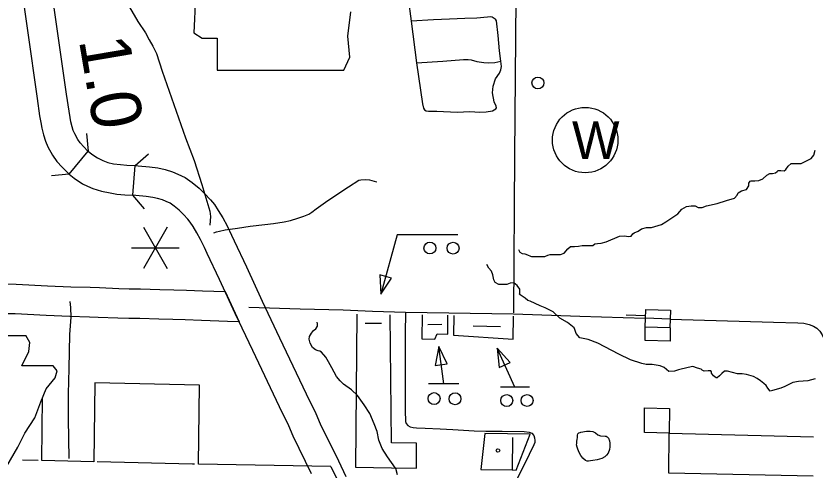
# Model space of a CAD drawing. Extents: x 1382482 to 1385815, y 1168351 to 1170484.
# Drawn here: x 1384529.1 to 1384797.7, y 1168845.5 to 1168998.2 of the extents above; entities that cross this region are included whole.
import ezdxf

# ---------------------------------------------------------------- set-up
doc = ezdxf.new("R2010")
doc.units = 0
for name, color, linetype in [('10', 7, 'Continuous'), ('15', 7, 'Continuous'), ('21', 7, 'Continuous'), ('35', 7, 'Continuous'), ('37', 7, 'Continuous'), ('48', 7, 'Continuous'), ('5', 7, 'Continuous'), ('57', 7, 'Continuous'), ('6', 7, 'Continuous'), ('Default', 7, 'Continuous')]:
    doc.layers.add(name, color=color, linetype=linetype)

msp = doc.modelspace()

# ---------------------------------------------------------------- linework, layer by layer
at = {"layer": '10'}
for points in [[(1384484.87, 1168906.51), (1384491.93, 1168906.82), (1384503.41, 1168907.42), (1384514, 1168907.87), (1384517.48, 1168907.94), (1384520.85, 1168908.05), (1384525.12, 1168908.05), (1384529.2, 1168908.01), (1384539.72, 1168907.46), (1384547.53, 1168907.11), (1384554.1, 1168906.93), (1384557.15, 1168906.82), (1384563.66, 1168906.54), (1384567.21, 1168906.44), (1384570.95, 1168906.4), (1384577.43, 1168906.23), (1384582.14, 1168906.12), (1384586.38, 1168905.98), (1384591.81, 1168905.76), (1384599.4, 1168905.49), (1384604.12, 1168895.31)], [(1384604.12, 1168895.31), (1384600.17, 1168895.45), (1384591.44, 1168895.77), (1384586.02, 1168895.98), (1384581.86, 1168896.12), (1384577.18, 1168896.23), (1384570.77, 1168896.4), (1384567.02, 1168896.44), (1384563.3, 1168896.55), (1384556.75, 1168896.83), (1384553.79, 1168896.94), (1384547.18, 1168897.11), (1384539.24, 1168897.47), (1384528.89, 1168898.01), (1384525.07, 1168898.05), (1384521.01, 1168898.05), (1384517.74, 1168897.94), (1384514.31, 1168897.87), (1384503.88, 1168897.43), (1384492.41, 1168896.83), (1384485.31, 1168896.52)]]:
    msp.add_lwpolyline(points, dxfattribs=at)
at = {"layer": '15'}
for points in [[(1384535.02, 1169049.94), (1384533.37, 1169049.02), (1384531.6, 1169048.43), (1384529.89, 1169048.1), (1384528.02, 1169048.07), (1384526.27, 1169048.27), (1384525.11, 1169048.58), (1384525.72, 1169044.13), (1384526.78, 1169036.05), (1384531.2, 1169005.95), (1384532.97, 1168993.24), (1384536.19, 1168970.39), (1384537.07, 1168964.62), (1384537.44, 1168962.3), (1384537.78, 1168960.47), (1384538.34, 1168958.17), (1384539.05, 1168956.06), (1384539.87, 1168954.17), (1384541.35, 1168951.36), (1384542.89, 1168949.25), (1384544.61, 1168947.32), (1384546.4, 1168945.48), (1384547.01, 1168944.97), (1384553.41, 1168952.66)], [(1384553.41, 1168952.66), (1384553.21, 1168952.83), (1384551.93, 1168954.14), (1384550.68, 1168955.54), (1384549.85, 1168956.67), (1384548.89, 1168958.5), (1384548.39, 1168959.64), (1384547.96, 1168960.94), (1384547.56, 1168962.59), (1384547.29, 1168964), (1384546.95, 1168966.15), (1384546.08, 1168971.84), (1384542.87, 1168994.63), (1384541.1, 1169007.37), (1384536.68, 1169037.42), (1384535.63, 1169045.46), (1384535.02, 1169049.94)], [(1384553.41, 1168952.66), (1384554.61, 1168951.66), (1384556.49, 1168950.44), (1384557.43, 1168949.97), (1384558.35, 1168949.57), (1384560.03, 1168948.89), (1384561.87, 1168948.5), (1384564.28, 1168948.18), (1384566.41, 1168948.02), (1384569.14, 1168947.83)], [(1384568.43, 1168937.86), (1384569.14, 1168947.83), (1384570.19, 1168947.76), (1384573.99, 1168947.4), (1384576.77, 1168947.05), (1384579.3, 1168946.52), (1384581.7, 1168945.73), (1384583.57, 1168945), (1384585.93, 1168943.88), (1384588.38, 1168942.21), (1384590.64, 1168940.31), (1384592.5, 1168938.5), (1384594.54, 1168936.35), (1384595.79, 1168934.72), (1384597.13, 1168932.73), (1384598.61, 1168930.25), (1384600.07, 1168927.56), (1384601.56, 1168924.49), (1384602.44, 1168922.51), (1384606.59, 1168913.8), (1384611.87, 1168902.32), (1384617.71, 1168889.98), (1384626.67, 1168871.09), (1384629.95, 1168864.5), (1384631.41, 1168861.06), (1384637.48, 1168848.56), (1384640.01, 1168843.27)], [(1384547.01, 1168944.97), (1384548.67, 1168943.59), (1384551.52, 1168941.74), (1384553.2, 1168940.9), (1384554.92, 1168940.16), (1384557.85, 1168939.29), (1384560.74, 1168938.66), (1384563.02, 1168938.24), (1384565.7, 1168938.05), (1384568.43, 1168937.86)], [(1384628.47, 1168844.22), (1384622.3, 1168856.93), (1384620.86, 1168860.32), (1384617.67, 1168866.72), (1384608.68, 1168885.7), (1384602.81, 1168898.09), (1384597.53, 1168909.56), (1384593.36, 1168918.33), (1384592.49, 1168920.28), (1384591.18, 1168922.99), (1384589.92, 1168925.3), (1384588.69, 1168927.37), (1384587.67, 1168928.88), (1384586.93, 1168929.85), (1384585.39, 1168931.46), (1384583.92, 1168932.89), (1384582.33, 1168934.23), (1384580.93, 1168935.19), (1384579.61, 1168935.82), (1384578.33, 1168936.31), (1384576.7, 1168936.84), (1384575.12, 1168937.18), (1384572.91, 1168937.45), (1384569.36, 1168937.79), (1384568.43, 1168937.86)]]:
    msp.add_lwpolyline(points, dxfattribs=at)
at = {"layer": '21'}
for p, q in [((1384590.29, 1169023.23), (1384588.94, 1168992.44)), ((1384640.71, 1168991.42), (1384641.72, 1168999.54)), ((1384588.94, 1168992.44), (1384591.65, 1168990.74)), ((1384591.65, 1168990.74), (1384596.72, 1168990.74)), ((1384596.72, 1168990.74), (1384596.72, 1168979.92)), ((1384641.38, 1168984.32), (1384640.71, 1168991.42)), ((1384639.35, 1168979.92), (1384641.38, 1168984.32)), ((1384596.72, 1168979.92), (1384639.35, 1168979.92)), ((1384533.8, 1168888.37), (1384532.39, 1168890.7)), ((1384533.46, 1168885.32), (1384533.8, 1168888.37)), ((1384531.09, 1168880.58), (1384533.46, 1168885.32)), ((1384541.58, 1168880.58), (1384531.09, 1168880.58)), ((1384542.93, 1168878.89), (1384541.58, 1168880.58)), ((1384542.25, 1168876.52), (1384542.93, 1168878.89)), ((1384539.21, 1168872.8), (1384542.25, 1168876.52)), ((1384537.52, 1168868.4), (1384539.21, 1168872.8)), ((1384535.49, 1168862.99), (1384537.52, 1168868.4)), ((1384532.1, 1168857.91), (1384535.49, 1168862.99)), ((1384529.74, 1168853.18), (1384532.1, 1168857.91)), ((1384526.01, 1168846.75), (1384529.74, 1168853.18))]:
    msp.add_line(p, q, dxfattribs=at)
msp.add_lwpolyline([(1384471.54, 1168890.73), (1384532.39, 1168890.7)], dxfattribs=at)
at = {"layer": '35'}
for points in [[(1384698.02, 1168919.63), (1384698.5, 1168918.76), (1384699.28, 1168918.29), (1384700.15, 1168918.21), (1384701.01, 1168917.9), (1384702.04, 1168917.42), (1384702.43, 1168917.34), (1384703.45, 1168917.34), (1384704.87, 1168917.27), (1384706.91, 1168917.34), (1384707.94, 1168917.74), (1384708.65, 1168917.97), (1384709.67, 1168917.97), (1384710.22, 1168917.97), (1384711.16, 1168917.97), (1384712.19, 1168917.97), (1384713.37, 1168918.45), (1384714.63, 1168919.86), (1384715.49, 1168920.65), (1384715.88, 1168920.65), (1384716.83, 1168920.65), (1384718.25, 1168920.73), (1384719.43, 1168921.04), (1384720.29, 1168921.04), (1384721.79, 1168921.04), (1384723.04, 1168921.04), (1384723.75, 1168921.52), (1384724.54, 1168921.67), (1384725.8, 1168921.75), (1384727.53, 1168922.22), (1384732.01, 1168924.11), (1384733.75, 1168924.27), (1384734.85, 1168924.04), (1384735.95, 1168924.11), (1384736.5, 1168924.9), (1384736.89, 1168925.29), (1384738.23, 1168925.77), (1384739.33, 1168926.55), (1384741.06, 1168927.03), (1384742.79, 1168927.03), (1384746.1, 1168928.05), (1384747.59, 1168928.91), (1384749.6, 1168930.33), (1384751.57, 1168931.67), (1384752.9, 1168933.17), (1384754.48, 1168934.11), (1384756.13, 1168934.35), (1384757.47, 1168934.35), (1384758.41, 1168933.8), (1384759.75, 1168933.8), (1384761.24, 1168934.27), (1384764.79, 1168935.13), (1384767.93, 1168936.08), (1384770.69, 1168936.94), (1384771.55, 1168937.89), (1384771.87, 1168938.75), (1384772.97, 1168939.38), (1384774.7, 1168939.78), (1384775.41, 1168941.04), (1384775.49, 1168941.98), (1384775.88, 1168942.61), (1384776.27, 1168942.77), (1384777.45, 1168942.77), (1384778.79, 1168942.85), (1384780.13, 1168943.4), (1384781.54, 1168944.66), (1384782.49, 1168945.21), (1384783.43, 1168945.21), (1384784.38, 1168945.37), (1384785.01, 1168945.84), (1384785.32, 1168946.15), (1384786.19, 1168946.15), (1384787.29, 1168946.07), (1384787.92, 1168946.55), (1384788.7, 1168947.65), (1384789.65, 1168948.51), (1384790.83, 1168948.59), (1384793.03, 1168948.51), (1384793.98, 1168948.99), (1384796.47, 1168950.22), (1384797.34, 1168951.4), (1384797.73, 1168953.05)], [(1384755.1, 1168879.93), (1384751.87, 1168879.23), (1384750.5, 1168878.71), (1384748.61, 1168878.65), (1384746.98, 1168880.02), (1384745.68, 1168880.54), (1384742.93, 1168880.93), (1384740.98, 1168880.93), (1384739.49, 1168881.29), (1384735.64, 1168882.53), (1384731.71, 1168884.45), (1384724.67, 1168888.11), (1384721.47, 1168889.35), (1384718.6, 1168889.93), (1384717.37, 1168891.44), (1384716.92, 1168892.74), (1384716.76, 1168893.29), (1384714.54, 1168895.12), (1384711.89, 1168896.52), (1384709.67, 1168898.68), (1384706.99, 1168900.05), (1384705.36, 1168900.7), (1384703.62, 1168901.48), (1384701.99, 1168902.26), (1384701.14, 1168902.53), (1384700.23, 1168903.24), (1384698.27, 1168904.61), (1384698.53, 1168904.81), (1384698.47, 1168906.31), (1384697.56, 1168907.55), (1384696.45, 1168908.4), (1384695.27, 1168908.33), (1384694.07, 1168907.91), (1384691.46, 1168907.88), (1384690.15, 1168908.53), (1384689.7, 1168909.41), (1384689.43, 1168911.11), (1384688.95, 1168912.31), (1384688.1, 1168913.36), (1384687.38, 1168914.6)], [(1384633.24, 1168883.46), (1384631.76, 1168885.14), (1384631.26, 1168885.41), (1384630.64, 1168885.56), (1384629.76, 1168885.87), (1384628.79, 1168886.64), (1384627.95, 1168888.14), (1384627.68, 1168889.45), (1384627.83, 1168890.41), (1384628.45, 1168891.53), (1384629.1, 1168892.38), (1384629.87, 1168892.99), (1384630.45, 1168893.88), (1384630.49, 1168894.61), (1384630.39, 1168895.26)], [(1384656.69, 1168846.16), (1384653.97, 1168849.95), (1384652.18, 1168852.73), (1384651.1, 1168855.58), (1384650.56, 1168858.43), (1384649.56, 1168861.05), (1384648.1, 1168864.52), (1384646.18, 1168867.37), (1384643.94, 1168870.6), (1384641.94, 1168872.45), (1384639.25, 1168874.37), (1384638.09, 1168875.45), (1384636.86, 1168876.99), (1384635.32, 1168879.84), (1384634.16, 1168881.92), (1384633.24, 1168883.46), (1384633.22, 1168883.52)], [(1384797.72, 1168876.14), (1384795.31, 1168875.43), (1384792.18, 1168875.3), (1384790.29, 1168874.91), (1384788.72, 1168874.19), (1384787.55, 1168873.6), (1384786.25, 1168873.01), (1384783.38, 1168872.23), (1384782.69, 1168872.03), (1384781.81, 1168873.01), (1384781.26, 1168873.86), (1384780.54, 1168874.55), (1384779.37, 1168875.46), (1384778.29, 1168876.28), (1384777.05, 1168876.93), (1384774.7, 1168877.58), (1384773.27, 1168877.78), (1384771.7, 1168877.78), (1384768.31, 1168878.75), (1384767.33, 1168878.69), (1384766.35, 1168877.91), (1384765.63, 1168877.12), (1384764.82, 1168876.54), (1384764.49, 1168876.54), (1384763.58, 1168877.12), (1384762.93, 1168878.1), (1384762.93, 1168878.56), (1384762.67, 1168878.89), (1384761.82, 1168878.89), (1384760.45, 1168878.76), (1384759.8, 1168879.08), (1384759.41, 1168879.41), (1384758.23, 1168879.73), (1384756.67, 1168880.26), (1384755.1, 1168879.93)], [(1384727.04, 1168849.98), (1384726.02, 1168849.36), (1384724.46, 1168848.94), (1384723.06, 1168848.71), (1384722.21, 1168848.61), (1384721.52, 1168848.51), (1384721.07, 1168848.51), (1384720.55, 1168848.67), (1384719.7, 1168849.46), (1384718.98, 1168850.34), (1384718.39, 1168851.35), (1384718.03, 1168852.46), (1384717.71, 1168853.21), (1384717.56, 1168853.99), (1384717.59, 1168854.41), (1384717.64, 1168855.07), (1384717.74, 1168855.82), (1384717.87, 1168856.31), (1384717.87, 1168856.9), (1384717.84, 1168857.22), (1384717.97, 1168857.61), (1384718.33, 1168857.97), (1384718.72, 1168858.13), (1384718.98, 1168858.17)], [(1384718.98, 1168858.17), (1384720.94, 1168858.59), (1384721.59, 1168858.59), (1384722.11, 1168858.59), (1384723.06, 1168858.43), (1384723.87, 1168857.97), (1384724.65, 1168857.35), (1384725.6, 1168856.99), (1384727.2, 1168856.83), (1384727.56, 1168856.83), (1384727.88, 1168856.63), (1384728.24, 1168856.18), (1384728.63, 1168855.36), (1384728.73, 1168854.55), (1384728.7, 1168853.24), (1384728.63, 1168852.36), (1384728.14, 1168851.12), (1384727.66, 1168850.53), (1384727.04, 1168849.98)], [(1384656.69, 1168846.16), (1384657.27, 1168843.99)]]:
    msp.add_lwpolyline(points, dxfattribs=at)
at = {"layer": '37'}
for points in [[(1384552.87, 1168958.63), (1384553.41, 1168952.66)], [(1384569.14, 1168947.83), (1384573.67, 1168951.76)], [(1384547.01, 1168944.97), (1384541.04, 1168944.43)], [(1384572.37, 1168933.33), (1384568.43, 1168937.86)]]:
    msp.add_lwpolyline(points, dxfattribs=at)
at = {"layer": '48'}
for p, q in [((1384579.98, 1168927.11), (1384571.98, 1168913.26)), ((1384571.98, 1168927.11), (1384579.98, 1168913.26)), ((1384567.98, 1168920.18), (1384583.98, 1168920.18))]:
    msp.add_line(p, q, dxfattribs=at)
at = {"layer": '5'}
for points in [[(1384696.04, 1168856.46), (1384695.96, 1168845.53)], [(1384536.56, 1168848.72), (1384531.3, 1168848.84)], [(1384589.08, 1168847.48), (1384588.44, 1168847.49), (1384556.36, 1168848.25)]]:
    msp.add_lwpolyline(points, dxfattribs=at)
at = {"layer": '57'}
for centre, radius in [((1384720.45, 1168956.42), 11), ((1384691.13, 1168852.05), 0.6)]:
    msp.add_circle(centre, radius, dxfattribs=at)
at = {"layer": '6'}
for points in [[(1384697.47, 1169056.99), (1384697.09, 1169004.13), (1384696.72, 1168951.26), (1384696.34, 1168898.39)], [(1384643.69, 1168897.91), (1384643.69, 1168897.91), (1384643.22, 1168846.49)], [(1384663.72, 1168846.12), (1384663.8, 1168854.52), (1384655.4, 1168854.67), (1384654.91, 1168897.64)], [(1384665.61, 1168897.68), (1384665.54, 1168889.55), (1384669.89, 1168889.46), (1384670.75, 1168891.28), (1384674.27, 1168891.21), (1384674.33, 1168897.51)], [(1384676.29, 1168897.49), (1384676.24, 1168890.89), (1384696.27, 1168889.53), (1384696.33, 1168897.22)], [(1384740.73, 1168897.39), (1384734.27, 1168897.53)], [(1384749.02, 1168893.25), (1384748.98, 1168888.85), (1384740.63, 1168889.04), (1384740.67, 1168893.5)], [(1384634.93, 1168846.64), (1384590.48, 1168847.46), (1384590.78, 1168874.02), (1384555.63, 1168874.8), (1384555.27, 1168848.28), (1384537.76, 1168848.69), (1384538.05, 1168869.81)], [(1384797.11, 1168843.4), (1384748.59, 1168844.42), (1384748.71, 1168857.85), (1384740.36, 1168858.07), (1384740.43, 1168866.39), (1384748.78, 1168866.2), (1384748.71, 1168857.85), (1384797.2, 1168856.6)], [(1384695.96, 1168845.53), (1384697.29, 1168845.5), (1384701.98, 1168857.5), (1384686.73, 1168857.75), (1384685.32, 1168845.72), (1384695.96, 1168845.53)], [(1384634.93, 1168846.64), (1384638.74, 1168838.82)], [(1384643.22, 1168846.49), (1384655.32, 1168846.27), (1384663.72, 1168846.12)]]:
    msp.add_lwpolyline(points, dxfattribs=at)
at = {"layer": 'Default'}
msp.add_line((1384749.13, 1168899.25), (1384748.96, 1168893.25), dxfattribs=at)
for points in [[(1384563.95, 1169006.34), (1384567.23, 1169001.13), (1384570.11, 1168996.33), (1384572.61, 1168992.46), (1384573.93, 1168990.16), (1384575.15, 1168988.01), (1384576.33, 1168985.51), (1384578.29, 1168979.59), (1384586.12, 1168957.2), (1384589, 1168949.61), (1384591.55, 1168941.5), (1384594.29, 1168932.5), (1384594.48, 1168930.69), (1384594.27, 1168927.77)], [(1384660.95, 1169004.14), (1384661.96, 1168996.37), (1384663.75, 1168982.46), (1384665.78, 1168968.63), (1384666.09, 1168967.19), (1384666.48, 1168966.64), (1384667.02, 1168966.29), (1384667.76, 1168966.14), (1384670.53, 1168966.1), (1384677.46, 1168965.87), (1384681.63, 1168966.02), (1384685.09, 1168965.87), (1384687.2, 1168965.94)], [(1384687.2, 1168965.94), (1384689.34, 1168966.26), (1384690.43, 1168966.92), (1384690.62, 1168967.23), (1384690.51, 1168967.89), (1384689.88, 1168969.26), (1384689.26, 1168972.37), (1384689.53, 1168974.56), (1384690.3, 1168976.97), (1384691.67, 1168978.96), (1384692.06, 1168980.01), (1384692.33, 1168981.18), (1384692.12, 1168982.95), (1384691.67, 1168986.44), (1384691.2, 1168991.58), (1384690.66, 1168996.49), (1384690.27, 1168997.04), (1384689.84, 1168997.35), (1384689.14, 1168997.78), (1384688.55, 1168997.89), (1384687.66, 1168997.74), (1384684.03, 1168997.47), (1384679.98, 1168997.27), (1384674.8, 1168997.11), (1384669.42, 1168996.88), (1384661.96, 1168996.37)], [(1384663.75, 1168982.46), (1384672.56, 1168982.93), (1384679.57, 1168983.52), (1384681.16, 1168983.56), (1384682.1, 1168983.4), (1384684.03, 1168982.85), (1384686.43, 1168982.48), (1384688.1, 1168982.37), (1384690.13, 1168982.52), (1384692.12, 1168982.95)], [(1384595.62, 1168925.28), (1384596.55, 1168925.61), (1384597.5, 1168925.86), (1384599.44, 1168926.25), (1384603.61, 1168926.78), (1384607.85, 1168927.45), (1384612.82, 1168928.05), (1384615.68, 1168928.4), (1384619.25, 1168928.93), (1384621.43, 1168929.36), (1384623.83, 1168930.13), (1384625.91, 1168930.88), (1384627.53, 1168931.55), (1384628.59, 1168932.18), (1384630.04, 1168933.28), (1384633.96, 1168936.1), (1384640.87, 1168940.72), (1384644.37, 1168942.91), (1384645.04, 1168943.12), (1384646.48, 1168943.15), (1384648, 1168943.05), (1384649.52, 1168942.66), (1384650.37, 1168942.38)], [(1384677.63, 1168924.61), (1384657.27, 1168924.61), (1384651.73, 1168904.63)], [(1384546.96, 1168849.41), (1384546.81, 1168862.7), (1384546.74, 1168871.1), (1384547.03, 1168879.65), (1384547.24, 1168891.02), (1384547.66, 1168896.87), (1384547.59, 1168900.19), (1384547.36, 1168902.11)], [(1384607.34, 1168900.2), (1384624.65, 1168899.71), (1384639.11, 1168899.39), (1384648.98, 1168898.92), (1384660.02, 1168898.57), (1384696.33, 1168897.97)], [(1384660.02, 1168898.57), (1384659.9, 1168891.29), (1384659.97, 1168879.04), (1384659.9, 1168865.54), (1384660.04, 1168861.79), (1384660.29, 1168861.16), (1384660.82, 1168860.49), (1384661.67, 1168860.06), (1384662.62, 1168859.78), (1384663.79, 1168859.71), (1384666.65, 1168859.57), (1384671.76, 1168859.39), (1384675.97, 1168859.14), (1384683.12, 1168858.68), (1384687.07, 1168858.58), (1384692.58, 1168858.54), (1384699.94, 1168858.47), (1384701.6, 1168858.26), (1384702.52, 1168857.87), (1384703.19, 1168857.13), (1384703.37, 1168856.32), (1384703.48, 1168855.47), (1384703.48, 1168854.76), (1384703.19, 1168853.99), (1384700.05, 1168847.45), (1384695.95, 1168839.32)], [(1384740.61, 1168893.5), (1384740.79, 1168899.49), (1384749.13, 1168899.25)], [(1384696.33, 1168897.97), (1384718.67, 1168897.27), (1384733.19, 1168896.76), (1384740.7, 1168896.5)], [(1384749.05, 1168896.25), (1384740.7, 1168896.5)], [(1384749.05, 1168896.25), (1384783.7, 1168895.16), (1384791.96, 1168894.93), (1384794, 1168894.85), (1384795.7, 1168894.42), (1384797.15, 1168893.87), (1384798.37, 1168893.2), (1384799.35, 1168892.17), (1384800.11, 1168890.98), (1384800.59, 1168889.94), (1384801.12, 1168887.3), (1384801.2, 1168885.96)], [(1384651.97, 1168894.74), (1384646.44, 1168894.74)], [(1384667.52, 1168894.45), (1384672.24, 1168894.5)], [(1384682.83, 1168893.93), (1384692.04, 1168893.79)], [(1384748.96, 1168893.25), (1384740.61, 1168893.5)], [(1384672.91, 1168874.51), (1384671.29, 1168886.98)], [(1384696.81, 1168873.36), (1384690.85, 1168886.41)], [(1384678.02, 1168874.51), (1384667.81, 1168874.51)], [(1384701.68, 1168873.36), (1384691.94, 1168873.36)]]:
    msp.add_lwpolyline(points, dxfattribs=at)
for points in [[(1384655.33, 1168909.99), (1384651.4, 1168911.08), (1384651.73, 1168904.63)], [(1384670.06, 1168880.65), (1384674.1, 1168881.17), (1384671.29, 1168886.98)], [(1384691.54, 1168879.99), (1384695.25, 1168881.69), (1384690.85, 1168886.41)]]:
    msp.add_lwpolyline(points, close=True, dxfattribs=at)
for centre in [(1384704.56, 1168975.63), (1384668.25, 1168920.13), (1384676.06, 1168920.09), (1384669.65, 1168869.51), (1384676.7, 1168869.44), (1384694.08, 1168868.86), (1384700.92, 1168868.87)]:
    msp.add_circle(centre, 2, dxfattribs=at)

# ---------------------------------------------------------------- texts
at = {"layer": '48'}
msp.add_text('1.0', height=16.896, rotation=279.6461, dxfattribs=at).set_placement((1384550.22, 1168990.08))
at = {"layer": '57'}
msp.add_text('W', height=12.67, dxfattribs=at).set_placement((1384716.01, 1168950.09))

doc.saveas('drawing.dxf')
